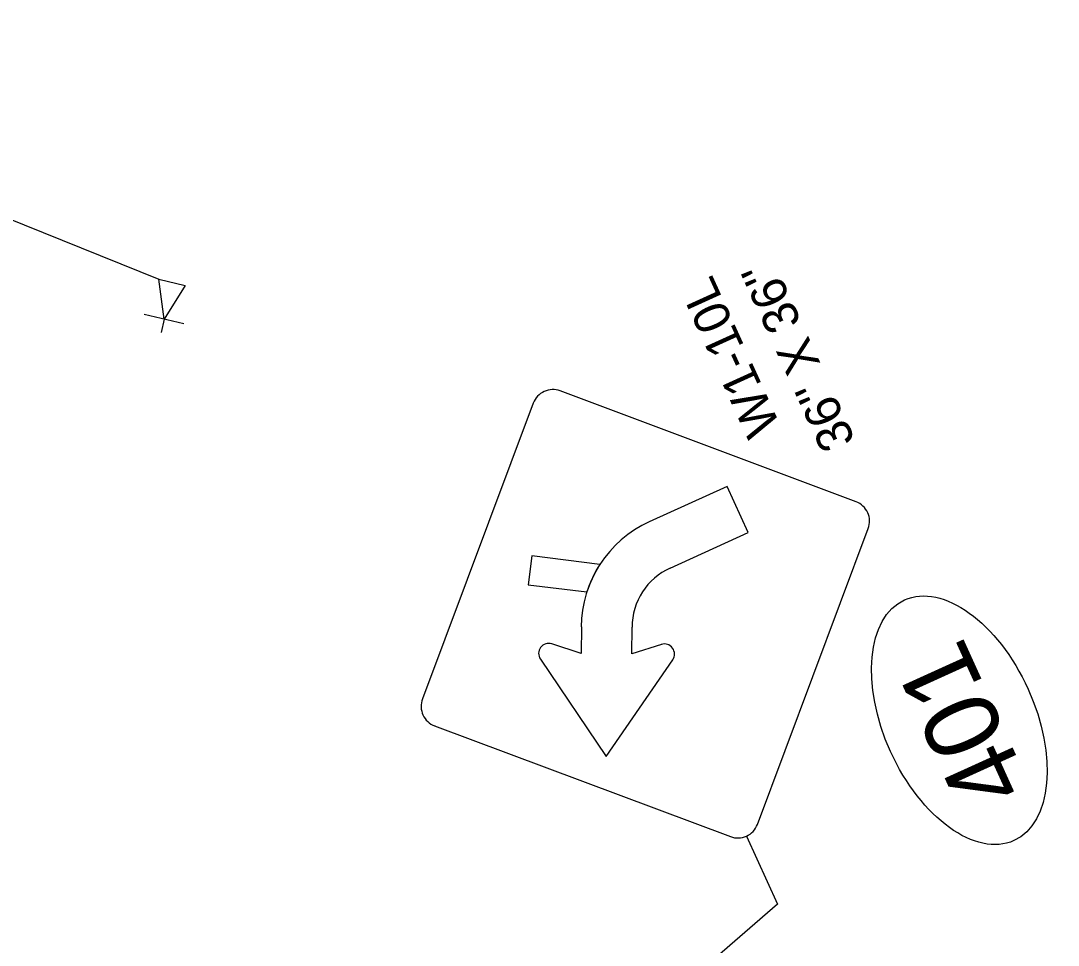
# Model space of a CAD drawing. Extents: x 2096999 to 2102576, y 682920 to 687015.
# Drawn here: x 2102135.1 to 2102309.1, y 683124.6 to 683279.8 of the extents above; entities that cross this region are included whole.
import ezdxf

# ---------------------------------------------------------------- set-up
doc = ezdxf.new("R2010")
doc.units = 0
doc.layers.add('Default', color=7, linetype='Continuous')

msp = doc.modelspace()

# ---------------------------------------------------------------- linework, layer by layer
at = {"layer": 'Default'}
for p, q in [((2102159.12, 683229.71), (2102158.22, 683236.39)), ((2102158.22, 683236.39), (2102162.67, 683235.34)), ((2102162.67, 683235.34), (2102159.12, 683229.71)), ((2102155.78, 683230.5), (2102162.41, 683228.94)), ((2102159.12, 683229.71), (2102158.59, 683227.46)), ((2102275.19, 683199.04), (2102225.56, 683217.64)), ((2102220.81, 683189.95), (2102220.21, 683185.13)), ((2102232.23, 683188.54), (2102220.81, 683189.95)), ((2102220.21, 683185.13), (2102230.03, 683183.91)), ((2102237.59, 683177.9), (2102237.58, 683177.87)), ((2102222.23, 683172.64), (2102222.24, 683172.64)), ((2102222.24, 683172.64), (2102233.26, 683156.33)), ((2102233.26, 683156.33), (2102244.44, 683172.54))]:
    msp.add_line(p, q, dxfattribs=at)
for points in [[(2102088.05, 683279.75), (2102096.47, 683261.26), (2102158.22, 683236.39)], [(2102221.05, 683215.59), (2102202.45, 683165.96)], [(2102244.02, 683187.93), (2102257.12, 683193.88), (2102253.6, 683201.62), (2102240.5, 683195.67)], [(2102258.64, 683144.91), (2102277.23, 683194.54)], [(2102229.12, 683178.06), (2102229.1, 683173.59), (2102224.16, 683175.21)], [(2102242.53, 683175.12), (2102237.6, 683173.55), (2102237.62, 683178.02)], [(2102204.5, 683161.46), (2102254.13, 683142.86)], [(2102256.81, 683142.95), (2102262.01, 683131.51), (2102160, 683043.07)]]:
    msp.add_lwpolyline(points, dxfattribs=at)
for centre, radius, start, end in [((2102224.33, 683214.37), 3.5, 69.458, 159.458), ((2102273.96, 683195.77), 3.5, 24.458, 69.458), ((2102273.96, 683195.77), 3.5, 339.458, 24.458), ((2102248.55, 683177.97), 19.45, 114.4274, 179.7345), ((2102248.55, 683177.97), 19.45, 147.081, 162.2078), ((2102248.55, 683177.97), 10.94, 114.4274, 179.7345), ((2102223.64, 683173.59), 1.7, 71.9367, 214.0587), ((2102243.04, 683173.5), 1.7, 325.4103, 107.5388), ((2102205.73, 683164.73), 3.5, 159.445, 204.4515), ((2102205.73, 683164.73), 3.5, 204.4515, 249.458), ((2102255.36, 683146.14), 3.5, 249.458, 339.458)]:
    msp.add_arc(centre, radius, start, end, dxfattribs=at)
msp.add_ellipse((2102292.52, 683162.39), major_axis=(9.17, -20.19), ratio=0.571429, dxfattribs=at)

# ---------------------------------------------------------------- texts
for s, height, rotation, p in [("36'' X 36''", 6, 114.458, (2102275.17, 683209.27)), ('W1-10L', 6, 114.458, (2102262.6, 683211.71)), ('401', 12.516, 114.4239, (2102304.44, 683151.28))]:
    msp.add_text(s, height=height, rotation=rotation, dxfattribs=at).set_placement(p)

doc.saveas('drawing.dxf')
